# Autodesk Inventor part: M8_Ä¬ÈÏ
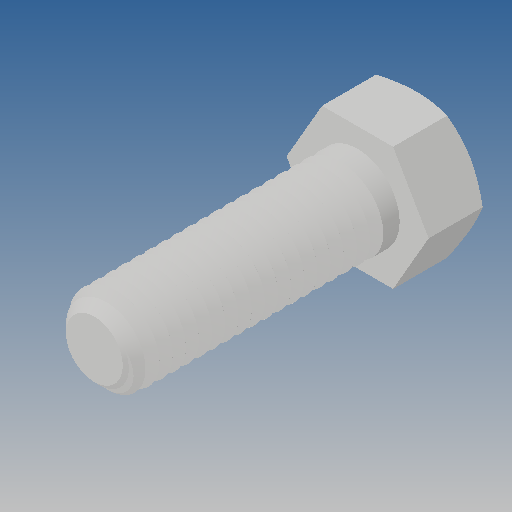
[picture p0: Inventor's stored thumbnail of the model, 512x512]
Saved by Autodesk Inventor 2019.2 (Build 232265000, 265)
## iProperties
Created: 2010-06
Part Number: M8_Ä¬ÈÏ
Material: Ogólny
Document SubType Name: Modeling
Designer: CADENGINEERING4
Density: 1 g/cm^3
Appearance: Domyślna
Author: CADENGINEERING4
Revision Number: ÈÎºÎ
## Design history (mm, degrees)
feature "NONE"
node "Bryła1"
